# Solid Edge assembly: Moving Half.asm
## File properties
Author: Dan
Template: metric assembly.asm
Last saved by: Dan
Revision: 73
Application: Solid Edge
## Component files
Ejector Pin.par
Spring Ejector.par
PB Dia 10-160.par
MH Die Plate.par
Support Plate.par
Riser.par
MH Clamping Plate.par
Ejector Clamping  Plate.par
Ejector Plate.par
LB FBN34-36.par
MH insert Outer.par
MH Insert Inner.par
SB M10-20.par
Support Pillar.par
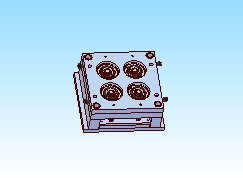
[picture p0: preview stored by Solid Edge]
